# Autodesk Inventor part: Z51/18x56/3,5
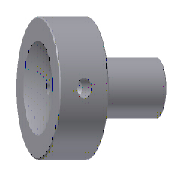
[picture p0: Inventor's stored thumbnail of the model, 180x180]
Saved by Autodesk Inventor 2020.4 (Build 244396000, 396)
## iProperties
Created: 2019-01
Part Number: Z51/18x56/3,5
Material: 1.2826
Description: Sprue Bushing
Document SubType Name: Modeling
Designer: mel
Standard Revision: 1
Manufacturer: HASCO
Language: fr-FR
Size Designation: 18x56/3,5
Categories: <MemberInstance><Categories><Category DisplayName="Moule" InternalName="349578f2-f4d4-4954-8c09-8e99297a61c0" Mnemonic="MOLD"><Category DisplayName="Canal d'inj
Density: 7.82 g/cm^3
Appearance: Par défaut
Mass: 449.949 g
Surface Area: 98.7904 cm^2
Volume: 57.5383 cm^3
IsCustomPart: 1
Author: mel
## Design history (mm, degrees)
sketch "Sketch1"
  geometry: L1 (0, -27.2)-(0, 23.2) reference; L2 (1.75, 18)-(19, 18); L3 (19, 18)-(19, 0); L4 (19, 0)-(12, 0); L5 (9, -3)-(9, -56); L6 (9, -56)-(3.688, -56); L7 (3.688, -56)-(1.75, 18); A1 r 3 centre (12, -3) between (12, 0) and (9, -3); 2 further points
  constraints: 12 end point, 3 parallel, 2 perpendicular, 2 point on circle, 2 point on line, 2 tangent, 1 centre point
  dimensions: "d0" = 18 diameter of L5 L1 (= D); "d3" = 38 diameter of L3 L1 (= d1); "d6" = 1.5 deg angle of L7 L1 (= 0.5 x Taper); "d7" = 18 distance between parallel lines of L4 L2 (= K_); "d8" = 56 distance between parallel lines of L4 L6 (= L); "d9" = 3 radius of A1 (= R3); "d62" = 3.5 diameter of point (1.75, 18) L1 (= d_); "d63" = 0 distance from line of point (1.75, 18) L2 (computed from Rd)
revolve "Revolution1" sketch "Sketch1" stored, may be unused: angle "d10" = 90 deg
sketch "Sketch2"
  geometry: L1 (0, -32.79)-(0, 56.739) reference; L2 (3.688, -56)-(1.75, 18) reference; L3 (-19, 18)-(19, 18) reference; L4 (0, 48.901)-(0, 17.901); A1 r 15.5 centre (0, 33.401) between (0, 17.901) and (0, 48.901); 2 further points
  constraints: 3 point on circle, 3 point on line, 2 end point, 1 centre point, 1 midpoint
  dimensions: "d64" = 0 distance from line of point (1.75, 18) L3 (computed from Rd); "d67" = 15.5 radius of A1 (= Rk)
revolve "Revolution2" sketch "Sketch2" stored, may be unused: angle "d13" = 90 deg
workplane "Work Plane1"
sketch "Sketch3"
  geometry: 2 further points
  constraints: 1 vertical alignment
  dimensions: "d43" = 9 distance of point (0, -9) point (0, 0) (= 0.5 x K_)
hole "Hole1" sketch "Sketch3" at (0, 0) diameter "d15" = 4 (= pd1); stored, may be unused: countersink angle "d19" = 90 deg, drill point angle "d21" = 118 deg; dims "d16" = 6, "d17" = 4, "d18" = 2, "d20" = 6 (= pl1)
chamfer "Chamfer1" distance "d22" = 0.3; stored, may be unused: second distance "d23" = 2, angle "d24" = 45 deg
sketch "Sketch4"
  geometry: L1 (0, -30.4)-(0, 42.4) reference; L2 (0, 36)-(19.5, 36); L3 (19.5, 36)-(19.5, 0); L4 (9, -56)-(0, -56); L5 (0, -56)-(0, 36); L6 (9, -3)-(9, -56); L7 (12, 0)-(19.5, 0); L8 (12, 0)-(9, -3); 2 further points
  constraints: 14 end point, 4 point on line, 2 horizontal, 2 parallel, 1 perpendicular, 1 vertical
  dimensions: "d56" = 3 distance of L7.start point (9, 0) (= R3_CS); "d57" = 3 distance of L6.start point (9, 0) (= d56); "d58" = 39 diameter of L3 L1 (= d1_CS); "d59" = 36 distance between parallel lines of L7 L2 (= K_CS); "d60" = 18 diameter of L6 L1 (= D_CS); "d61" = 56 distance between parallel lines of L7 L4 (= L_CS)
feature "RevolutionSrf1" sketch "Sketch4" dims angle "d33" = 90 deg
feature "Sculpter1"
feature "Scission3"
body "Solid1"
body "Srf1"
feature "Surface1"
body "Srf2"
other parameters: "L" = 56 [user parameter; used in 1 equation term], "d1" = 38 [user parameter; used in 1 equation term], "d_" = 3.5 [user parameter; used in 1 equation term], "D" = 18 [user parameter; used in 1 equation term], "K_" = 18 [user parameter; used in 2 equation terms], "R" = 0 [user parameter], "Taper" = 3 deg [user parameter; used in 1 equation term], "Rd" = 0 [user parameter; used in 2 equation terms], "R3" = 3 [user parameter; used in 1 equation term], "pd1" = 4 [user parameter; used in 1 equation term], "d1_CS" = 39 [user parameter; used in 1 equation term], "K_CS" = 36 [user parameter; used in 1 equation term], "d44" = 0, "d45" = 0, "d46" = 0, "L_CS" = 56 [user parameter; used in 1 equation term], "D_CS" = 18 [user parameter; used in 1 equation term], "pl1" = 6 [user parameter; used in 1 equation term], "R3_CS" = 3 [user parameter; used in 1 equation term], "Rk" = 15.5 [user parameter; used in 1 equation term]
